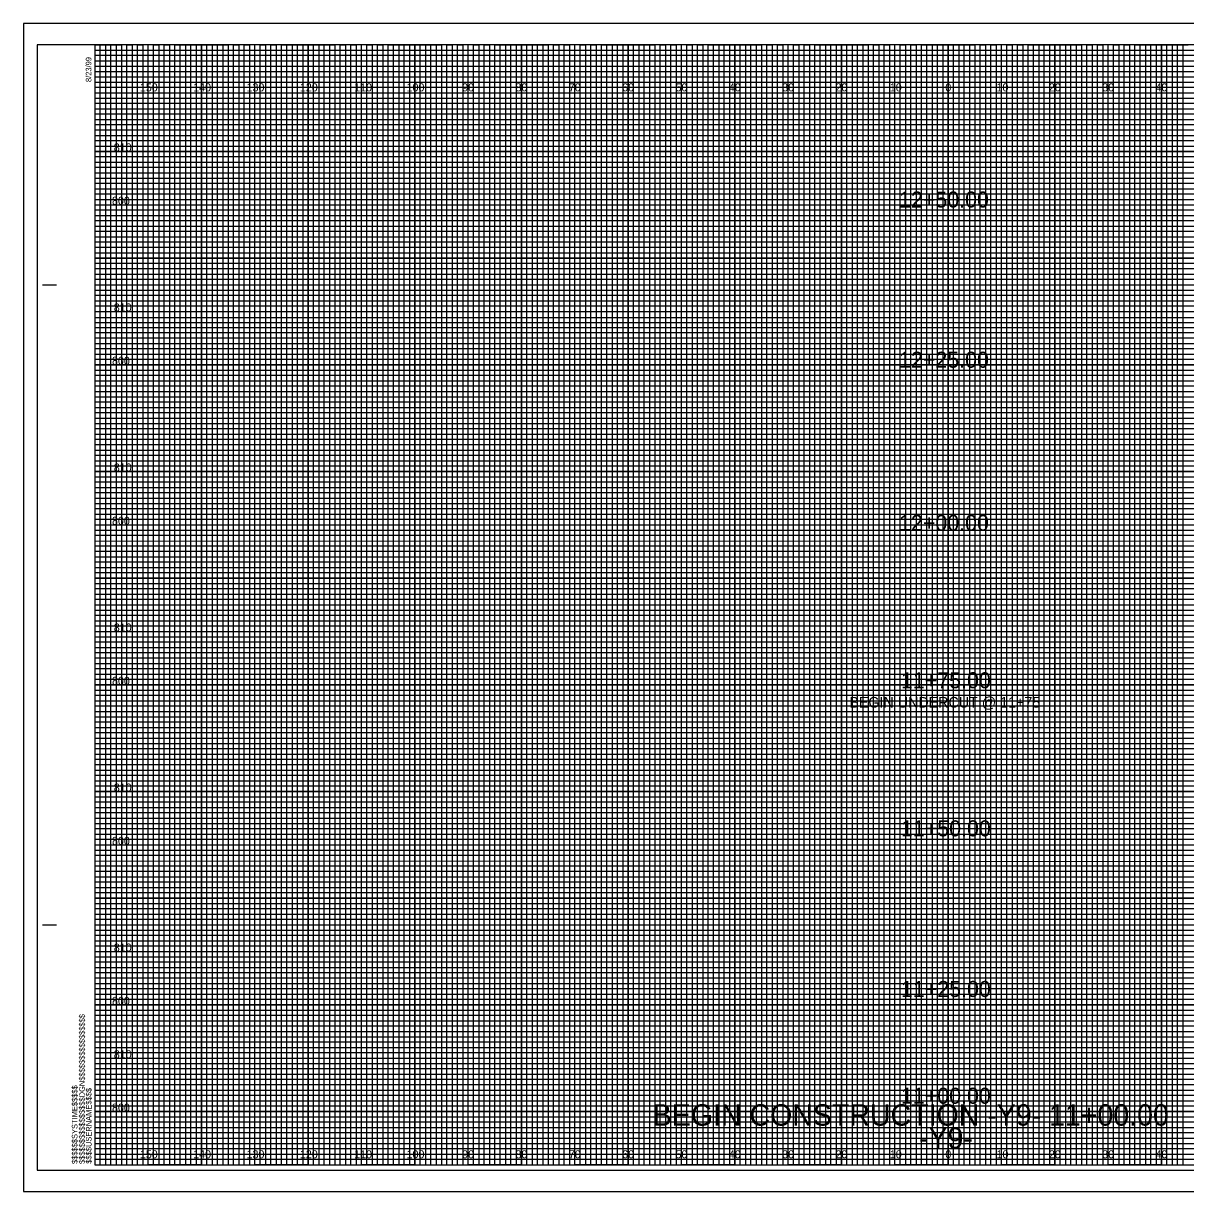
# Model space of a CAD drawing. Extents: x -13 to 323, y -5 to 214.
# Drawn here: x -13.4 to 204.5, y -5 to 214 of the extents above; entities that cross this region are included whole.
import ezdxf

# ---------------------------------------------------------------- set-up
doc = ezdxf.new("R2010")
doc.units = 0
for name, color, linetype in [('Prop Grid Mask', 7, 'Continuous'), ('Prop XS Alignment Label', 7, 'Continuous'), ('Prop XS Elevation Labels', 7, 'Continuous'), ('Prop XS Offset Labels', 7, 'Continuous'), ('Prop XS Station Labels', 7, 'Continuous'), ('Sheet Cross Section CELL', 7, 'Continuous'), ('Sheet Cross Section Grid Major CELL', 7, 'Continuous'), ('Sheet Cross Section Grid Middle CELL', 7, 'Continuous'), ('Sheet Cross Section Grid Minor 1 CELL', 7, 'Continuous'), ('Sheet Cross Section Grid Minor 2 CELL', 7, 'Continuous'), ('Sheet Cutting Line CELL', 7, 'Continuous'), ('Sheet DOT Grid CELL', 7, 'Continuous'), ('Sheet Plot Border Inside CELL', 7, 'Continuous'), ('Sheet Plot Border Outside CELL', 7, 'Continuous')]:
    doc.layers.add(name, color=color, linetype=linetype)

msp = doc.modelspace()

# ---------------------------------------------------------------- linework, layer by layer
at = {"layer": 'Sheet Cross Section CELL'}
for p, q in [((-9.8, 165), (-7.3, 165)), ((-9.7, 165), (-7.2, 165)), ((-9.8, 45), (-7.3, 45)), ((-9.7, 45), (-7.2, 45)), ((0, 0), (0, 0)), ((0, 0), (0, 0)), ((0, 0), (0, 0)), ((0, 0), (0, 0)), ((0, 0), (0, 0)), ((0, 0), (0, 0)), ((0, 0), (0, 0))]:
    msp.add_line(p, q, dxfattribs=at)
msp.add_lwpolyline([(320, 210), (0, 210), (0, 0), (320, 0)], close=True, dxfattribs=at)
at = {"layer": 'Sheet Cross Section Grid Major CELL'}
for p, q in [((10, 210), (0, 210)), ((10, 0), (10, 210)), ((30, 210), (20, 210)), ((20, 210), (20, 0)), ((30, 0), (30, 210)), ((50, 210), (40, 210)), ((40, 210), (40, 0)), ((50, 0), (50, 210)), ((70, 210), (60, 210)), ((60, 210), (60, 0)), ((70, 0), (70, 210)), ((90, 210), (80, 210)), ((80, 210), (80, 0)), ((90, 0), (90, 210)), ((110, 210), (100, 210)), ((100, 210), (100, 0)), ((110, 0), (110, 210)), ((130, 210), (120, 210)), ((120, 210), (120, 0)), ((130, 0), (130, 210)), ((150, 210), (140, 210)), ((140, 210), (140, 0)), ((150, 0), (150, 210)), ((170, 210), (160, 210)), ((160, 210), (160, 0)), ((170, 0), (170, 210)), ((190, 210), (180, 210)), ((180, 210), (180, 0)), ((190, 0), (190, 210)), ((210, 210), (200, 210)), ((200, 210), (200, 0)), ((20, 0), (10, 0)), ((40, 0), (30, 0)), ((60, 0), (50, 0)), ((80, 0), (70, 0)), ((100, 0), (90, 0)), ((120, 0), (110, 0)), ((140, 0), (130, 0)), ((160, 0), (150, 0)), ((180, 0), (170, 0)), ((200, 0), (190, 0))]:
    msp.add_line(p, q, dxfattribs=at)
for points in [[(0, 200), (320, 200), (320, 190), (0, 190)], [(0, 180), (320, 180), (320, 170), (0, 170)], [(0, 160), (320, 160), (320, 150), (0, 150)], [(0, 140), (320, 140), (320, 130), (0, 130)], [(0, 120), (320, 120), (320, 110), (0, 110)], [(0, 100), (320, 100), (320, 90), (0, 90)], [(0, 80), (320, 80), (320, 70), (0, 70)], [(0, 60), (320, 60), (320, 50), (0, 50)], [(0, 40), (320, 40), (320, 30), (0, 30)], [(0, 20), (320, 20), (320, 10), (0, 10)]]:
    msp.add_lwpolyline(points, dxfattribs=at)
at = {"layer": 'Sheet Cross Section Grid Middle CELL'}
for points in [[(0, 210), (5, 210), (5, 0), (15, 0), (15, 210), (25, 210), (25, 0), (35, 0), (35, 210), (45, 210), (45, 0), (55, 0), (55, 210), (65, 210), (65, 0), (75, 0), (75, 210), (85, 210), (85, 0), (95, 0), (95, 210), (105, 210), (105, 0), (115, 0), (115, 210), (125, 210), (125, 0), (135, 0), (135, 210), (145, 210), (145, 0), (155, 0), (155, 210), (165, 210), (165, 0), (175, 0), (175, 210), (185, 210), (185, 0), (195, 0), (195, 210), (205, 210)], [(0, 205), (275, 205)], [(0, 185), (320, 185), (320, 195), (0, 195)], [(0, 165), (320, 165), (320, 175), (0, 175)], [(0, 145), (320, 145), (320, 155), (0, 155)], [(0, 125), (320, 125), (320, 135), (0, 135)], [(0, 105), (320, 105), (320, 115), (0, 115)], [(0, 85), (320, 85), (320, 95), (0, 95)], [(0, 65), (320, 65), (320, 75), (0, 75)], [(0, 45), (320, 45), (320, 55), (0, 55)], [(0, 25), (320, 25), (320, 35), (0, 35)], [(0, 5), (320, 5), (320, 15), (0, 15)]]:
    msp.add_lwpolyline(points, dxfattribs=at)
at = {"layer": 'Sheet Cross Section Grid Minor 1 CELL'}
for p, q in [((0, 209), (260, 209)), ((260, 207.98), (0, 207.98)), ((0, 207.98), (0, 207)), ((0, 207), (260, 207)), ((260, 205.89), (0, 205.89)), ((0, 205.89), (0, 204)), ((0, 204), (320, 204))]:
    msp.add_line(p, q, dxfattribs=at)
for points in [[(0, 203), (270, 203), (320, 203), (320, 202), (0, 202)], [(0, 201), (320, 201), (320, 199), (0, 199)], [(0, 198), (320, 198), (320, 197), (0, 196.98)], [(0, 196), (320, 196), (320, 194), (0, 194)], [(0, 193), (320, 193), (320, 192), (0, 192)], [(0, 191), (320, 191), (320, 189), (0, 189)], [(0, 188), (320, 188), (320, 187), (0, 187)], [(0, 186), (320, 186), (320, 184), (0, 184)], [(0, 183), (320, 183), (320, 182), (0, 182)], [(0, 181), (320, 181), (320, 179), (0, 179)], [(0, 178), (320, 178), (320, 177), (0, 177)], [(0, 176), (320, 176), (320, 173.95), (320, 173), (320, 172), (0, 172)], [(0, 174), (320, 174), (320, 173), (0, 173)], [(0, 171), (320, 171), (320, 169), (0, 169.03)], [(0, 169.03), (320, 169), (320, 168), (0, 168)], [(0, 167), (320, 167), (320, 166), (0, 166)], [(0, 164), (320, 164), (320, 163), (0, 163)], [(0, 162), (320, 162), (320, 161), (0, 161)], [(-0.07, 158.89), (320, 158.89), (320, 157.88), (-0.07, 157.88)], [(0, 157), (320, 157), (320, 156), (0, 156)], [(0, 154), (320, 154), (320, 153), (0, 153)], [(0, 152), (320, 152), (320, 151), (0, 151)], [(0, 149), (320, 149), (320, 148), (0, 148)], [(0, 147), (320, 147), (320, 146), (0, 146)], [(0, 144), (320, 144), (320, 143), (0, 143)], [(0, 142), (320, 142), (320, 141), (0, 141)], [(0, 139), (320, 139), (319.99, 137.98), (0, 138)], [(0, 137), (320, 137), (320, 136), (0, 136)], [(0, 134), (320, 134), (320, 133), (0, 133)], [(0, 132), (320, 132), (320, 131), (0, 131)], [(0, 129), (320, 129), (320, 128), (0, 128)], [(0, 127), (320, 127), (320, 126), (0, 126)], [(0, 124), (320, 124), (320, 123), (0, 123)], [(0, 122), (320, 122), (320, 121), (0, 121)], [(0, 119), (320, 119), (320, 118), (0, 118)], [(0, 116.99), (320.07, 116.91), (320, 116), (0, 116)], [(0, 114), (320, 114), (320, 113), (0, 113)], [(0, 112), (320, 112), (320, 111), (0, 111)], [(0, 109), (320, 109), (320, 108), (0, 108)], [(0, 107), (320, 107), (320, 106), (0, 106)], [(0, 104), (320, 104), (320, 103), (0, 103)], [(0, 102), (320, 102), (320, 101), (0, 101)], [(0, 99), (320, 99), (320, 98), (0, 98)], [(0, 97), (320, 97), (320, 96), (0, 96)], [(0, 94), (320, 94), (320, 93), (0, 93)], [(0, 92), (320, 92), (320, 91), (0, 91)], [(0, 89), (320, 89), (320, 88), (0, 88)], [(0, 87), (320, 87), (320, 86), (0, 86)], [(0, 84), (320, 84), (320, 83), (0, 83)], [(0, 82), (320, 82), (320, 81), (0, 81)], [(0, 79), (320, 79), (319.99, 77.98), (0, 78)], [(0, 77), (320, 77), (320, 76), (0, 76)], [(0, 74), (320, 74), (320, 73), (0, 73)], [(0, 72), (320, 72), (320, 71), (0, 71)], [(0, 69), (320, 69), (320, 68), (0, 68)], [(0, 67), (320, 67), (320, 66), (0, 66)], [(0, 64), (320, 64), (320, 63), (0, 63)], [(0, 62), (320, 62), (320, 61), (0, 61)], [(0, 59), (320, 59), (320, 58), (0, 58)], [(0, 56.99), (320.07, 56.91), (320, 56), (0, 56)], [(0, 54), (320, 54), (320, 53), (0, 53)], [(0, 52), (320, 52), (320, 51), (0, 51)], [(0, 49), (320, 49), (320, 48), (0, 48)], [(0, 47), (320, 47), (320, 46), (0, 46)], [(0, 44), (320, 44), (320, 43), (0, 43)], [(0, 42), (320, 42), (320, 41), (0, 41)], [(0, 39), (320, 39), (320, 38), (0, 38)], [(0, 37), (320, 37), (320, 36), (0, 36)], [(0, 34), (320, 34), (320, 33), (0, 33)], [(0, 32), (320, 32), (320, 31), (0, 31)], [(0, 29), (320, 29), (320, 28), (0, 28)], [(0, 27), (320, 27), (320, 26), (0, 26)], [(0, 24), (320, 24), (320, 23), (0, 23)], [(0, 22), (320, 22), (320, 21), (0, 21)], [(0, 19), (320, 19), (320, 18), (0, 18)], [(0, 17), (320, 17), (320, 16), (0, 16)], [(0, 14), (320, 14), (320, 13), (0, 13)], [(0, 12), (320, 12), (320, 11), (0, 11)], [(0, 9), (320, 9), (320, 8), (0, 8)], [(0, 7), (320, 7), (320, 6), (0, 6)], [(0, 4), (320, 4), (320, 3), (0, 3)], [(0, 2), (320, 2), (320, 1), (0, 1)]]:
    msp.add_lwpolyline(points, dxfattribs=at)
at = {"layer": 'Sheet Cross Section Grid Minor 2 CELL'}
for points in [[(0, 0), (1, 0), (1, 210), (2, 210), (2, 0)], [(2, 0), (3, 0), (3, 210), (4, 210), (4, 0)], [(5, 0), (6, 0), (6, 210), (7, 210), (7, 0)], [(7, 0), (8, 0), (8, 210), (9, 210), (9, 0)], [(10, 0), (11, 0), (11, 210), (12, 210), (12, 0)], [(12, 0), (13, 0), (13, 210), (14, 210), (14, 0)], [(15, 0), (16, 0), (16, 210), (17, 210), (17, 0)], [(17, 0), (18, 0), (18, 210), (19, 210), (19, 0)], [(20, 0), (21, 0), (21, 210), (22, 210), (22, 0)], [(22, 0), (23, 0), (23, 210), (24, 210), (24, 0)], [(25, 0), (26, 0), (26, 210), (27, 210), (27, 0)], [(27, 0), (28, 0), (28, 210), (29, 210), (29, 0)], [(30, 0), (31, 0), (31, 210), (32, 210), (32, 0)], [(32, 0), (33, 0), (33, 210), (34, 210), (34, 0)], [(35, 0), (36, 0), (36, 210), (37, 210), (37, 0)], [(37, 0), (38, 0), (38, 210), (39, 210), (39, 0)], [(40, 0), (41, 0), (41, 210), (42, 210), (42, 0)], [(42, 0), (43, 0), (43, 210), (44, 210), (44, 0)], [(45, 0), (46, 0), (46, 210), (47, 210), (47, 0)], [(47, 0), (48, 0), (48, 210), (49, 210), (49, 0)], [(50, 0), (51, 0), (51, 210), (52, 210), (52, 0)], [(52, 0), (53, 0), (53, 210), (54, 210), (54, 0)], [(55, 0), (56, 0), (56, 210), (57, 210), (57, 0)], [(57, 0), (58, 0), (58, 210), (59, 210), (59, 0)], [(60, 0), (61, 0), (61, 210), (62, 210), (62, 0)], [(62, 0), (63, 0), (63, 210), (64, 210), (64, 0)], [(65, 0), (66, 0), (66, 210), (67, 210), (67, 0)], [(67, 0), (68, 0), (68, 210), (69, 210), (69, 0)], [(70, 0), (71, 0), (71, 210), (72, 210), (72, 0)], [(72, 0), (73, 0), (73, 210), (74, 210), (74, 0)], [(75, 0), (76, 0), (76, 210), (77, 210), (77, 0)], [(77, 0), (78, 0), (78, 210), (79, 210), (79, 0)], [(80, 0), (81, 0), (81, 210), (82, 210), (82, 0)], [(82, 0), (83, 0), (83, 210), (84, 210), (84, 0)], [(85, 0), (86, 0), (86, 210), (87, 210), (87, 0)], [(87, 0), (88, 0), (88, 210), (89, 210), (89, 0)], [(90, 0), (91, 0), (91, 210), (92, 210), (92, 0)], [(92, 0), (93, 0), (93, 210), (94, 210), (94, 0)], [(95, 0), (96, 0), (96, 210), (97, 210), (97, 0)], [(97, 0), (98, 0), (98, 210), (99, 210), (99, 0)], [(100, 0), (101, 0), (101, 210), (102, 210), (102, 0)], [(102, 0), (103, 0), (103, 210), (104, 210), (104, 0)], [(105, 0), (106, 0), (106, 210), (107, 210), (107, 0)], [(107, 0), (108, 0), (108, 210), (109, 210), (109, 0)], [(110, 0), (111, 0), (111, 210), (112, 210), (112, 0)], [(112, 0), (113, 0), (113, 210), (114, 210), (114, 0)], [(115, 0), (116, 0), (116, 210), (117, 210), (117, 0)], [(117, 0), (118, 0), (118, 210), (119, 210), (119, 0)], [(120, 0), (121, 0), (121, 210), (122, 210), (122, 0)], [(122, 0), (123, 0), (123, 210), (124, 210), (124, 0)], [(125, 0), (126, 0), (126, 210), (127, 210), (127, 0)], [(127, 0), (128, 0), (128, 210), (129, 210), (129, 0)], [(130, 0), (131, 0), (131, 210), (132, 210), (132, 0)], [(132, 0), (133, 0), (133, 210), (134, 210), (134, 0)], [(135, 0), (136, 0), (136, 210), (137, 210), (137, 0)], [(137, 0), (138, 0), (138, 210), (139, 210), (139, 0)], [(140, 0), (141, 0), (141, 210), (142, 210), (142, 0)], [(142, 0), (143, 0), (143, 210), (144, 210), (144, 0)], [(145, 0), (146, 0), (146, 210), (147, 210), (147, 0)], [(147, 0), (148, 0), (148, 210), (149, 210), (149, 0)], [(150, 0), (151, 0), (151, 210), (152, 210), (152, 0)], [(152, 0), (153, 0), (153, 210), (154, 210), (154, 0)], [(155, 0), (156, 0), (156, 210), (157, 210), (157, 0)], [(157, 0), (158, 0), (158, 210), (159, 210), (159, 0)], [(160, 0), (161, 0), (161, 210), (162, 210), (162, 0)], [(162, 0), (163, 0), (163, 210), (164, 210), (164, 0)], [(165, 0), (166, 0), (166, 210), (167, 210), (167, 0)], [(167, 0), (168, 0), (168, 210), (169, 210), (169, 0)], [(170, 0), (171, 0), (171, 210), (172, 210), (172, 0)], [(172, 0), (173, 0), (173, 210), (174, 210), (174, 0)], [(175, 0), (176, 0), (176, 210), (177, 210), (177, 0)], [(177, 0), (178, 0), (178, 210), (179, 210), (179, 0)], [(180, 0), (181, 0), (181, 210), (182, 210), (182, 0)], [(182, 0), (183, 0), (183, 210), (184, 210), (184, 0)], [(185, 0), (186, 0), (186, 210), (187, 210), (187, 0)], [(187, 0), (188, 0), (188, 210), (189, 210), (189, 0)], [(190, 0), (191, 0), (191, 210), (192, 210), (192, 0)], [(192, 0), (193, 0), (193, 210), (194, 210), (194, 0)], [(195, 0), (196, 0), (196, 210), (197, 210), (197, 0)], [(197, 0), (198, 0), (198, 210), (199, 210), (199, 0)], [(200, 0), (201, 0), (201, 210), (202, 210), (202, 0)], [(202, 0), (203, 0), (203, 210), (204, 210), (204, 0)]]:
    msp.add_lwpolyline(points, dxfattribs=at)
at = {"layer": 'Sheet Cutting Line CELL'}
for p, q in [((323.3, 214), (-13.4, 214)), ((-13.4, 214), (-13.4, -5)), ((-13.4, -5), (323.3, -5))]:
    msp.add_line(p, q, dxfattribs=at)
at = {"layer": 'Sheet DOT Grid CELL'}
for p, q in [((10, 0), (10, 210)), ((20, 0), (20, 210)), ((30, 0), (30, 210)), ((40, 0), (40, 210)), ((50, 0), (50, 210)), ((60, 0), (60, 210)), ((70, 0), (70, 210)), ((80, 0), (80, 210)), ((90, 0), (90, 210)), ((100, 0), (100, 210)), ((110, 0), (110, 210)), ((120, 0), (120, 210)), ((130, 0), (130, 210)), ((140, 0), (140, 210)), ((150, 0), (150, 210)), ((160, 0), (160, 210)), ((170, 0), (170, 210)), ((180, 0), (180, 210)), ((190, 0), (190, 210)), ((200, 0), (200, 210)), ((0, 200), (320, 200)), ((0, 190), (320, 190)), ((0, 180), (320, 180)), ((0, 170), (320, 170)), ((0, 160), (320, 160)), ((0, 150), (320, 150)), ((0, 140), (320, 140)), ((0, 130), (320, 130)), ((0, 120), (320, 120)), ((0, 110), (320, 110)), ((0, 100), (320, 100)), ((0, 90), (320, 90)), ((0, 80), (320, 80)), ((0, 70), (320, 70)), ((0, 60), (320, 60)), ((0, 50), (320, 50)), ((0, 40), (320, 40)), ((0, 30), (320, 30)), ((0, 20), (320, 20)), ((0, 10), (320, 10))]:
    msp.add_line(p, q, dxfattribs=at)
at = {"layer": 'Sheet Plot Border Inside CELL'}
msp.add_lwpolyline([(-10.8, -1), (322.4, -1), (322.4, 210), (-10.8, 210)], close=True, dxfattribs=at)
at = {"layer": 'Sheet Plot Border Outside CELL'}
msp.add_lwpolyline([(-13.4, -5), (323.3, -5), (323.3, 214), (-13.4, 214)], close=True, dxfattribs=at)

# ---------------------------------------------------------------- texts
at = {"layer": 'Prop Grid Mask'}
msp.add_text('BEGIN UNDERCUT @ 11+75', height=2, dxfattribs=at).set_placement((141.46, 85.73))
at = {"layer": 'Prop XS Alignment Label'}
for s, p in [('BEGIN CONSTRUCTION -Y9- 11+00.00', (104.6, 7.37)), ('-Y9-', (154.52, 3.04))]:
    msp.add_text(s, height=4, dxfattribs=at).set_placement(p)
at = {"layer": 'Prop XS Elevation Labels'}
for s, p in [('810', (3.55, 190)), ('800', (3.22, 180)), ('810', (3.55, 160)), ('800', (3.22, 150)), ('810', (3.55, 130)), ('800', (3.22, 120)), ('810', (3.55, 100)), ('800', (3.22, 90)), ('810', (3.55, 70)), ('800', (3.22, 60)), ('810', (3.55, 40)), ('800', (3.22, 30)), ('810', (3.55, 20)), ('800', (3.22, 10))]:
    msp.add_text(s, height=1.5, dxfattribs=at).set_placement(p)
at = {"layer": 'Prop XS Offset Labels'}
for s, p in [('150', (8.44, 201.25)), ('140', (18.44, 201.25)), ('130', (28.44, 201.25)), ('120', (38.44, 201.25)), ('110', (48.62, 201.25)), ('100', (58.44, 201.25)), ('90', (68.86, 201.25)), ('80', (78.86, 201.25)), ('70', (88.86, 201.25)), ('60', (98.86, 201.25)), ('50', (108.86, 201.25)), ('40', (118.86, 201.25)), ('30', (128.86, 201.25)), ('20', (138.86, 201.25)), ('10', (149.04, 201.25)), ('0', (159.45, 201.25)), ('0', (159.45, 201.25)), ('10', (169.04, 201.25)), ('20', (178.86, 201.25)), ('30', (188.86, 201.25)), ('40', (198.86, 201.25)), ('150', (8.44, 1.25)), ('140', (18.44, 1.25)), ('130', (28.44, 1.25)), ('120', (38.44, 1.25)), ('110', (48.62, 1.25)), ('100', (58.44, 1.25)), ('90', (68.86, 1.25)), ('80', (78.86, 1.25)), ('70', (88.86, 1.25)), ('60', (98.86, 1.25)), ('50', (108.86, 1.25)), ('40', (118.86, 1.25)), ('30', (128.86, 1.25)), ('20', (138.86, 1.25)), ('10', (149.04, 1.25)), ('0', (159.45, 1.25)), ('0', (159.45, 1.25)), ('10', (169.04, 1.25)), ('20', (178.86, 1.25)), ('30', (188.86, 1.25)), ('40', (198.86, 1.25))]:
    msp.add_text(s, height=1.5, dxfattribs=at).set_placement(p)
at = {"layer": 'Prop XS Station Labels'}
for s, p in [('12+50.00', (150.77, 179.48)), ('12+25.00', (150.77, 149.45)), ('12+00.00', (150.77, 118.87)), ('11+75.00', (151.13, 89.36)), ('11+50.00', (151.13, 61.6)), ('11+25.00', (151.13, 31.49)), ('11+00.00', (151.13, 11.48))]:
    msp.add_text(s, height=3, dxfattribs=at).set_placement(p)
at = {"layer": 'Sheet Cross Section CELL'}
for s, p in [('8/23/99', (-0.65, 203)), ('$$$$$$$$$$$$$$$$DGN$$$$$$$$$$$$$$$$', (-1.88, 0.18)), ('$$$$$$SYSTIME$$$$$', (-3.26, 0.18)), ('$$$$USERNAME$$$$', (-0.62, 0.23))]:
    msp.add_text(s, height=1.05, rotation=90, dxfattribs=at).set_placement(p)

doc.saveas('drawing.dxf')
